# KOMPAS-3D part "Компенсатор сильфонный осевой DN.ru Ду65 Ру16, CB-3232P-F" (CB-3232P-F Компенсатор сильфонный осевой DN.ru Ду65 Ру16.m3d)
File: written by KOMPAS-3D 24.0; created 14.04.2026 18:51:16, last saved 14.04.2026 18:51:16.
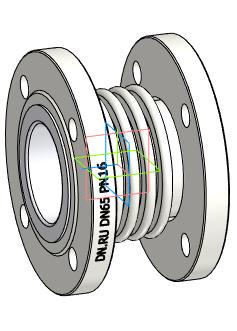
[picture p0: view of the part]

Document properties: Автор: DN.RU; Полное имя файла: D:\PROJECT CAD\DN.RU\..199(ACTUALE). CB-3232P-F Компенсатор сильфонный осевой DN.ru\Исходники\DN65\CB-3232P-F Компенсатор сильфонный осевой DN.ru Ду65 Ру16.m3d

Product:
- Body: Твердое тело1  | qty 1
    Масса: 7.947575
- Part/product: Компенсатор сильфонный осевой DN.ru Ду65 Ру16  | designation CB-3232P-F
    Масса: 6.3
    Раздел спецификации: Прочие изделия
    Комментарий: D140-02139
    Примечание: D140-02139
    additional columns: Типовые

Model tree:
1. Твердое тело1  (labels: Твердое тело1)

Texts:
  CB-3232P-F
